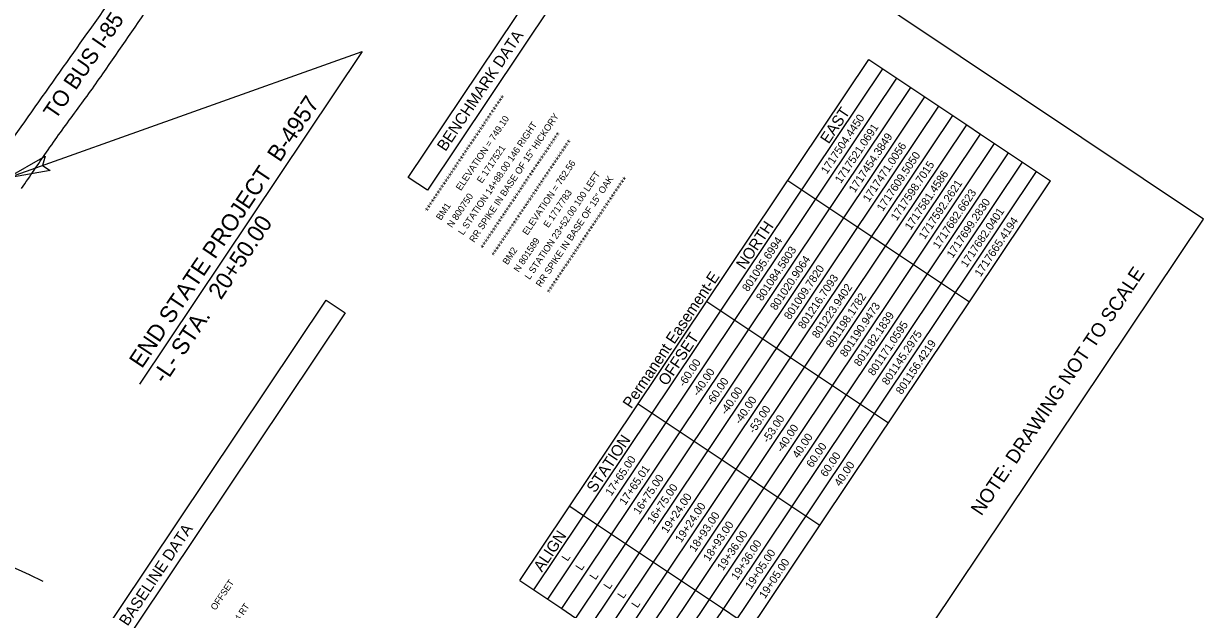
# Model space of a CAD drawing. Extents: x 1716977 to 1718461, y 800056 to 801805.
# Drawn here: x 1717724 to 1718461, y 801029 to 801395 of the extents above; entities that cross this region are included whole.
import ezdxf

# ---------------------------------------------------------------- set-up
doc = ezdxf.new("R2010")
doc.units = 0
for name, color, linetype in [('CTL Sheet Border CELL', 7, 'Continuous'), ('CTL Sheet Notes CELL', 7, 'Continuous'), ('CTL Sheet Table Cell', 7, 'Continuous'), ('CTL Sheet Text', 7, 'Continuous'), ('Exist Hydro Jurisdictional Stream or Body of Water', 7, 'Continuous'), ('Exist Roads EOP', 7, 'Continuous'), ('Prop DSN Text', 7, 'Continuous'), ('Prop Terminator CELL', 7, 'Continuous'), ('Sheet Data Field CELL', 7, 'Continuous')]:
    doc.layers.add(name, color=color, linetype=linetype)

msp = doc.modelspace()

# ---------------------------------------------------------------- linework, layer by layer
at = {"layer": 'CTL Sheet Border CELL'}
for points in [[(1717702.35, 801780.65), (1716976.84, 800696.7), (1717735.6, 800188.84), (1718461.11, 801272.8)], [(1717964.52, 801299.01), (1718042.51, 801415.52), (1718054.41, 801407.56), (1717976.43, 801291.06)], [(1717691.02, 800890.37), (1717913.14, 801222.23), (1717925.03, 801214.27), (1717702.93, 800882.43)]]:
    msp.add_lwpolyline(points, close=True, dxfattribs=at)
at = {"layer": 'CTL Sheet Table Cell'}
for p, q in [((1718034.15, 801046.99), (1718252.19, 801372.75)), ((1718252.19, 801372.75), (1718260.91, 801366.91)), ((1718042.87, 801041.15), (1718260.91, 801366.91)), ((1718260.91, 801366.91), (1718269.64, 801361.07)), ((1718051.6, 801035.31), (1718269.64, 801361.07)), ((1718269.64, 801361.07), (1718278.36, 801355.23)), ((1718060.33, 801029.47), (1718278.36, 801355.23)), ((1718069.05, 801023.63), (1718287.09, 801349.39)), ((1718278.36, 801355.23), (1718287.09, 801349.39)), ((1718287.09, 801349.39), (1718295.82, 801343.55)), ((1718077.78, 801017.79), (1718295.82, 801343.55)), ((1718295.82, 801343.55), (1718304.54, 801337.71)), ((1718086.5, 801011.94), (1718304.54, 801337.71)), ((1718304.54, 801337.71), (1718313.27, 801331.87)), ((1718095.23, 801006.1), (1718313.27, 801331.87)), ((1718313.27, 801331.87), (1718321.99, 801326.03)), ((1718103.95, 801000.26), (1718321.99, 801326.03)), ((1718112.68, 800994.42), (1718330.72, 801320.19)), ((1718321.99, 801326.03), (1718330.72, 801320.19)), ((1718330.72, 801320.19), (1718339.45, 801314.35)), ((1718121.41, 800988.58), (1718339.45, 801314.35)), ((1718339.45, 801314.35), (1718348.17, 801308.51)), ((1718130.13, 800982.74), (1718348.17, 801308.51)), ((1718348.17, 801308.51), (1718356.9, 801302.67)), ((1718138.86, 800976.9), (1718356.9, 801302.67)), ((1718356.9, 801302.67), (1718365.62, 801296.83)), ((1718147.58, 800971.06), (1718365.62, 801296.83)), ((1718201.57, 801297.13), (1718210.3, 801291.29)), ((1718210.3, 801291.29), (1718219.02, 801285.45)), ((1718219.02, 801285.45), (1718227.75, 801279.61)), ((1718227.75, 801279.61), (1718236.47, 801273.77)), ((1718236.47, 801273.77), (1718245.2, 801267.93)), ((1718245.2, 801267.93), (1718253.93, 801262.09)), ((1718253.93, 801262.09), (1718262.65, 801256.25)), ((1718262.65, 801256.25), (1718271.38, 801250.41)), ((1718271.38, 801250.41), (1718280.1, 801244.57)), ((1718280.1, 801244.57), (1718288.83, 801238.72)), ((1718288.83, 801238.72), (1718297.56, 801232.88)), ((1718297.56, 801232.88), (1718306.28, 801227.04)), ((1718306.28, 801227.04), (1718315.01, 801221.2)), ((1718150.95, 801221.5), (1718159.68, 801215.66)), ((1718159.68, 801215.66), (1718168.41, 801209.82)), ((1718168.41, 801209.82), (1718177.13, 801203.98)), ((1718177.13, 801203.98), (1718185.86, 801198.14)), ((1718185.86, 801198.14), (1718194.58, 801192.3)), ((1718194.58, 801192.3), (1718203.31, 801186.46)), ((1718203.31, 801186.46), (1718212.04, 801180.62)), ((1718212.04, 801180.62), (1718220.76, 801174.78)), ((1718220.76, 801174.78), (1718229.49, 801168.94)), ((1718229.49, 801168.94), (1718238.21, 801163.1)), ((1718108.13, 801157.51), (1718116.85, 801151.67)), ((1718238.21, 801163.1), (1718246.94, 801157.26)), ((1718246.94, 801157.26), (1718255.66, 801151.42)), ((1718116.85, 801151.67), (1718125.58, 801145.83)), ((1718255.66, 801151.42), (1718264.39, 801145.58)), ((1718125.58, 801145.83), (1718134.3, 801139.99)), ((1718134.3, 801139.99), (1718143.03, 801134.15)), ((1718143.03, 801134.15), (1718151.75, 801128.31)), ((1718151.75, 801128.31), (1718160.48, 801122.47)), ((1718160.48, 801122.47), (1718169.21, 801116.63)), ((1718169.21, 801116.63), (1718177.93, 801110.79)), ((1718177.93, 801110.79), (1718186.66, 801104.95)), ((1718186.66, 801104.95), (1718195.38, 801099.11)), ((1718195.38, 801099.11), (1718204.11, 801093.27)), ((1718065.3, 801093.52), (1718074.02, 801087.68)), ((1718204.11, 801093.27), (1718212.84, 801087.43)), ((1718074.02, 801087.68), (1718082.75, 801081.84)), ((1718212.84, 801087.43), (1718221.56, 801081.59)), ((1718082.75, 801081.84), (1718091.47, 801076)), ((1718091.47, 801076), (1718100.2, 801070.16)), ((1718100.2, 801070.16), (1718108.93, 801064.32)), ((1718108.93, 801064.32), (1718117.65, 801058.48)), ((1718117.65, 801058.48), (1718126.38, 801052.64)), ((1718034.15, 801046.99), (1718042.87, 801041.15)), ((1718126.38, 801052.64), (1718135.1, 801046.8)), ((1718135.1, 801046.8), (1718143.83, 801040.96)), ((1718042.87, 801041.15), (1718051.6, 801035.31)), ((1718143.83, 801040.96), (1718152.55, 801035.12)), ((1718051.6, 801035.31), (1718060.33, 801029.47)), ((1718152.55, 801035.12), (1718161.28, 801029.28)), ((1718060.33, 801029.47), (1718069.05, 801023.63)), ((1718161.28, 801029.28), (1718170.01, 801023.44))]:
    msp.add_line(p, q, dxfattribs=at)
at = {"layer": 'CTL Sheet Text'}
msp.add_line((1717935.61, 801377.63), (1717796.58, 801169.79), dxfattribs=at)
at = {"layer": 'Exist Hydro Jurisdictional Stream or Body of Water'}
for points in [[(1717605.94, 801111.76), (1717612.79, 801109.04), (1717616.17, 801107.46), (1717622.88, 801104.61), (1717634.87, 801098.17), (1717639.69, 801095.36), (1717644.84, 801093.04), (1717654.93, 801089.79), (1717659.08, 801087.53), (1717662.76, 801085.55), (1717665.17, 801083.21), (1717674.36, 801077.27), (1717683.55, 801072), (1717698.55, 801063.91), (1717727.72, 801050.92)], [(1717727.61, 801050.97), (1717727.72, 801050.92), (1717736.2, 801046.69)]]:
    msp.add_lwpolyline(points, dxfattribs=at)
at = {"layer": 'Exist Roads EOP'}
for points in [[(1717704.66, 801304.87), (1717720.57, 801327.61), (1717755.53, 801377.08), (1717788.31, 801423.35), (1717810.22, 801454.82)], [(1717723, 801292.11), (1717738.53, 801314.79), (1717747.21, 801327.08), (1717756.08, 801339.25), (1717764.97, 801351.4), (1717773.68, 801363.68), (1717805.81, 801410.44), (1717827.75, 801442.62)]]:
    msp.add_spline(points, degree=3, dxfattribs=at)
at = {"layer": 'Prop DSN Text'}
msp.add_line((1717713.83, 801298.49), (1717935.61, 801377.63), dxfattribs=at)
at = {"layer": 'Prop Terminator CELL'}
msp.add_lwpolyline([(1717740.81, 801303.27), (1717713.83, 801298.49), (1717737.74, 801312.21), (1717736.13, 801306.53)], close=True, dxfattribs=at)

# ---------------------------------------------------------------- texts
at = {"layer": 'CTL Sheet Notes CELL'}
for s, p in [('EAST', (1718227.07, 801319.49)), ('NORTH', (1718174.52, 801240.98)), ('Permanent Easement-E', (1718103.73, 801154.09)), ('OFFSET', (1718125.87, 801168.29)), ('STATION', (1718081.11, 801101.41)), ('ALIGN', (1718047.98, 801051.92))]:
    msp.add_text(s, height=7, rotation=56.20506, dxfattribs=at).set_placement(p)
at = {"layer": 'CTL Sheet Text'}
for s, height, rotation, p in [('TO BUS I-85', 10, 55.59655, (1717744.13, 801334.6)), ('BENCHMARK DATA', 7.0434, 56.20506, (1717987.77, 801314.84)), ('END STATE PROJECT  B-4957', 10.4343, 56.20505, (1717798.1, 801179.1)), ('****************************************', 4.1667, 56.20506, (1717978, 801276.49)), ('BM1       ELEVATION = 749.10', 4.1667, 56.20506, (1717984.92, 801271.86)), ('L STATION 14+88.00 146 RIGHT', 4.1667, 56.20506, (1717998.77, 801262.59)), ('RR SPIKE IN BASE OF 15" HICKORY', 4.1667, 56.20506, (1718005.7, 801257.95)), ('1717504.4450', 5, 56.20506, (1718225.95, 801300.74)), ('****************************************', 4.1667, 56.20506, (1718012.62, 801253.31)), ('1717521.0691', 5, 56.20506, (1718234.68, 801294.9)), ('****************************************', 4.1667, 56.20506, (1718019.55, 801248.68)), ('1717454.3849', 5, 56.20506, (1718243.4, 801289.06)), ('1717471.0056', 5, 56.20506, (1718252.13, 801283.22)), ('N 800750      E 1717521', 4.1667, 56.20506, (1717991.85, 801267.22)), ('1717609.5050', 5, 56.20506, (1718260.85, 801277.38)), ('BM2       ELEVATION = 762.56', 4.1667, 56.20506, (1718026.47, 801244.04)), ('1717598.7015', 5, 56.20506, (1718269.58, 801271.54)), ('L STATION 23+52.00 100 LEFT', 4.1667, 56.20506, (1718040.32, 801234.77)), ('RR SPIKE IN BASE OF 15" OAK', 4.1667, 56.20506, (1718047.25, 801230.14)), ('****************************************', 4.1667, 56.20506, (1718054.17, 801225.5)), ('1717581.4586', 5, 56.20506, (1718278.31, 801265.7)), ('N 801589      E 1717783', 4.1667, 56.20506, (1718033.4, 801239.41)), ('1717592.2621', 5, 56.20506, (1718287.03, 801259.86)), ('1717682.6623', 5, 56.20506, (1718295.76, 801254.02)), ('1717699.2830', 5, 56.20506, (1718304.48, 801248.18)), ('1717682.0401', 5, 56.20506, (1718313.21, 801242.34)), ('20+50.00', 10.434, 56.20506, (1717847.47, 801222.02)), ('1717665.4194', 5, 56.20506, (1718321.93, 801236.5)), ('801095.6994', 5, 56.20506, (1718176.71, 801227.18)), ('801084.5803', 5, 56.20506, (1718185.44, 801221.34)), ('801020.9064', 5, 56.20506, (1718194.17, 801215.5)), ('801009.7820', 5, 56.20506, (1718202.89, 801209.66)), ('801216.7093', 5, 56.20506, (1718211.62, 801203.82)), ('801223.9402', 5, 56.20506, (1718220.34, 801197.98)), ('801198.1782', 5, 56.20506, (1718229.07, 801192.14)), ('801190.9473', 5, 56.20506, (1718237.79, 801186.3)), ('-L- STA. ', 10.434, 56.20505, (1717812.55, 801169.43)), ('801182.1839', 5, 56.20506, (1718246.52, 801180.46)), ('801171.0595', 5, 56.20506, (1718255.25, 801174.62)), ('801145.2975', 5, 56.20506, (1718263.97, 801168.78)), ('801156.4219', 5, 56.20506, (1718272.7, 801162.93)), ('-60.00', 5, 56.20506, (1718136.89, 801167.68)), ('-40.00', 5, 56.20506, (1718145.61, 801161.84)), ('-60.00', 5, 56.20506, (1718154.34, 801156)), ('-40.00', 5, 56.20506, (1718163.07, 801150.16)), ('-40.00', 5, 56.20506, (1718171.79, 801144.32)), ('-53.00', 5, 56.20506, (1718180.52, 801138.48)), ('-53.00', 5, 56.20506, (1718189.24, 801132.64)), ('-40.00', 5, 56.20506, (1718197.97, 801126.8)), ('40.00', 5, 56.20506, (1718208.08, 801123.02)), ('60.00', 5, 56.20506, (1718216.8, 801117.18)), ('17+65.00', 5, 56.20506, (1718091.3, 801099.57)), ('60.00', 5, 56.20506, (1718225.53, 801111.34)), ('40.00', 5, 56.20506, (1718234.25, 801105.5)), ('17+65.01', 5, 56.20506, (1718100.03, 801093.73)), ('16+75.00', 5, 56.20506, (1718108.75, 801087.89)), ('16+75.00', 5, 56.20506, (1718117.48, 801082.04)), ('19+24.00', 5, 56.20506, (1718126.2, 801076.2)), ('19+24.00', 5, 56.20506, (1718134.93, 801070.36)), ('18+93.00', 5, 56.20506, (1718143.66, 801064.52)), ('18+93.00', 5, 56.20506, (1718152.38, 801058.68)), ('BASELINE DATA', 7.0434, 56.20506, (1717789.18, 801018.13)), ('19+36.00', 5, 56.20506, (1718161.11, 801052.84)), ('19+36.00', 5, 56.20506, (1718169.83, 801047)), ('L', 5, 56.20506, (1718063.97, 801058.73)), ('19+05.00', 5, 56.20506, (1718178.56, 801041.16)), ('L', 5, 56.20506, (1718072.69, 801052.89)), ('19+05.00', 5, 56.20506, (1718187.28, 801035.32)), ('    POINT          DESC.           NORTH             EAST          ELEVATION           L STATION       OFFSET', 4.05, 56.20506, (1717719.37, 800841.8)), ('L', 5, 56.20506, (1718081.42, 801047.05)), ('L', 5, 56.20506, (1718090.15, 801041.21)), ('3                        BL-3      800522.8022     1717105.5535           782.85         10+58.71         24.44 RT', 4.05, 56.20506, (1717732.83, 800832.79)), ('L', 5, 56.20506, (1718098.87, 801035.37)), ('L', 5, 56.20506, (1718107.6, 801029.53))]:
    msp.add_text(s, height=height, rotation=rotation, dxfattribs=at).set_placement(p)
at = {"layer": 'Sheet Data Field CELL'}
msp.add_text('NOTE: DRAWING NOT TO SCALE', height=8.6956, rotation=56.09981, dxfattribs=at).set_placement((1718322.44, 801087.05))

doc.saveas('drawing.dxf')
